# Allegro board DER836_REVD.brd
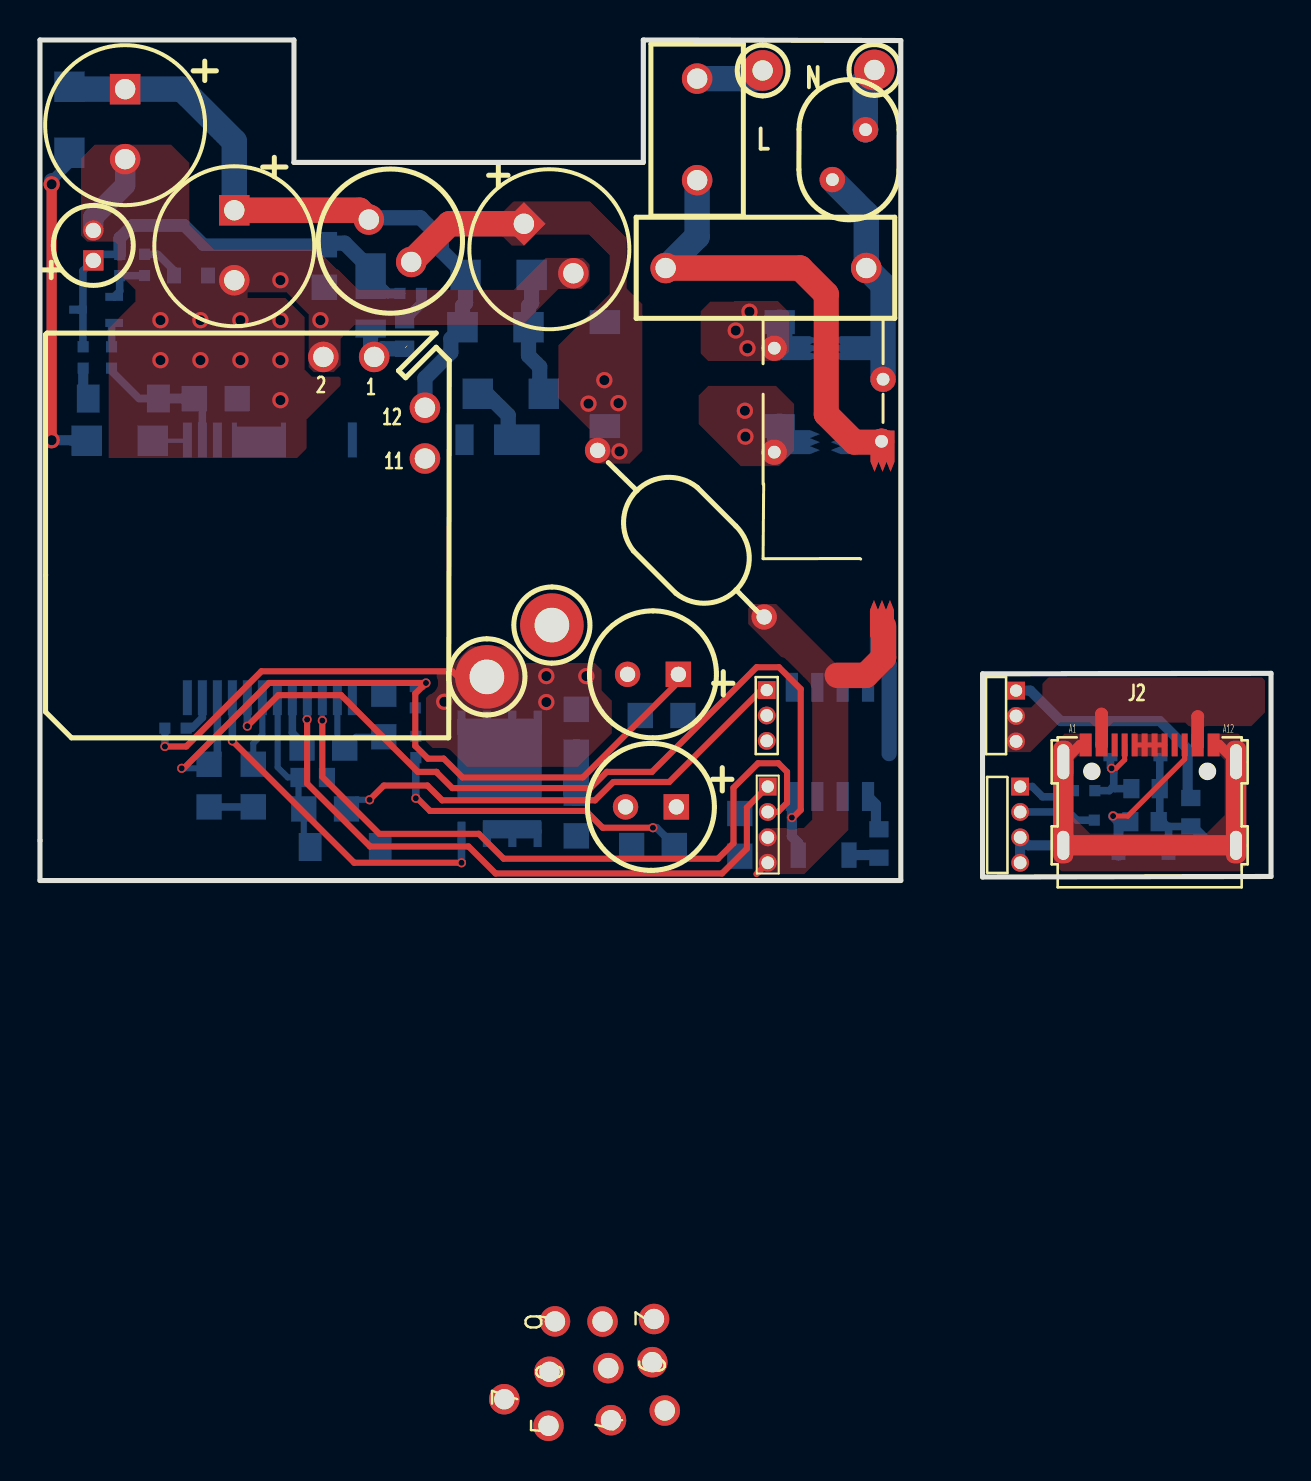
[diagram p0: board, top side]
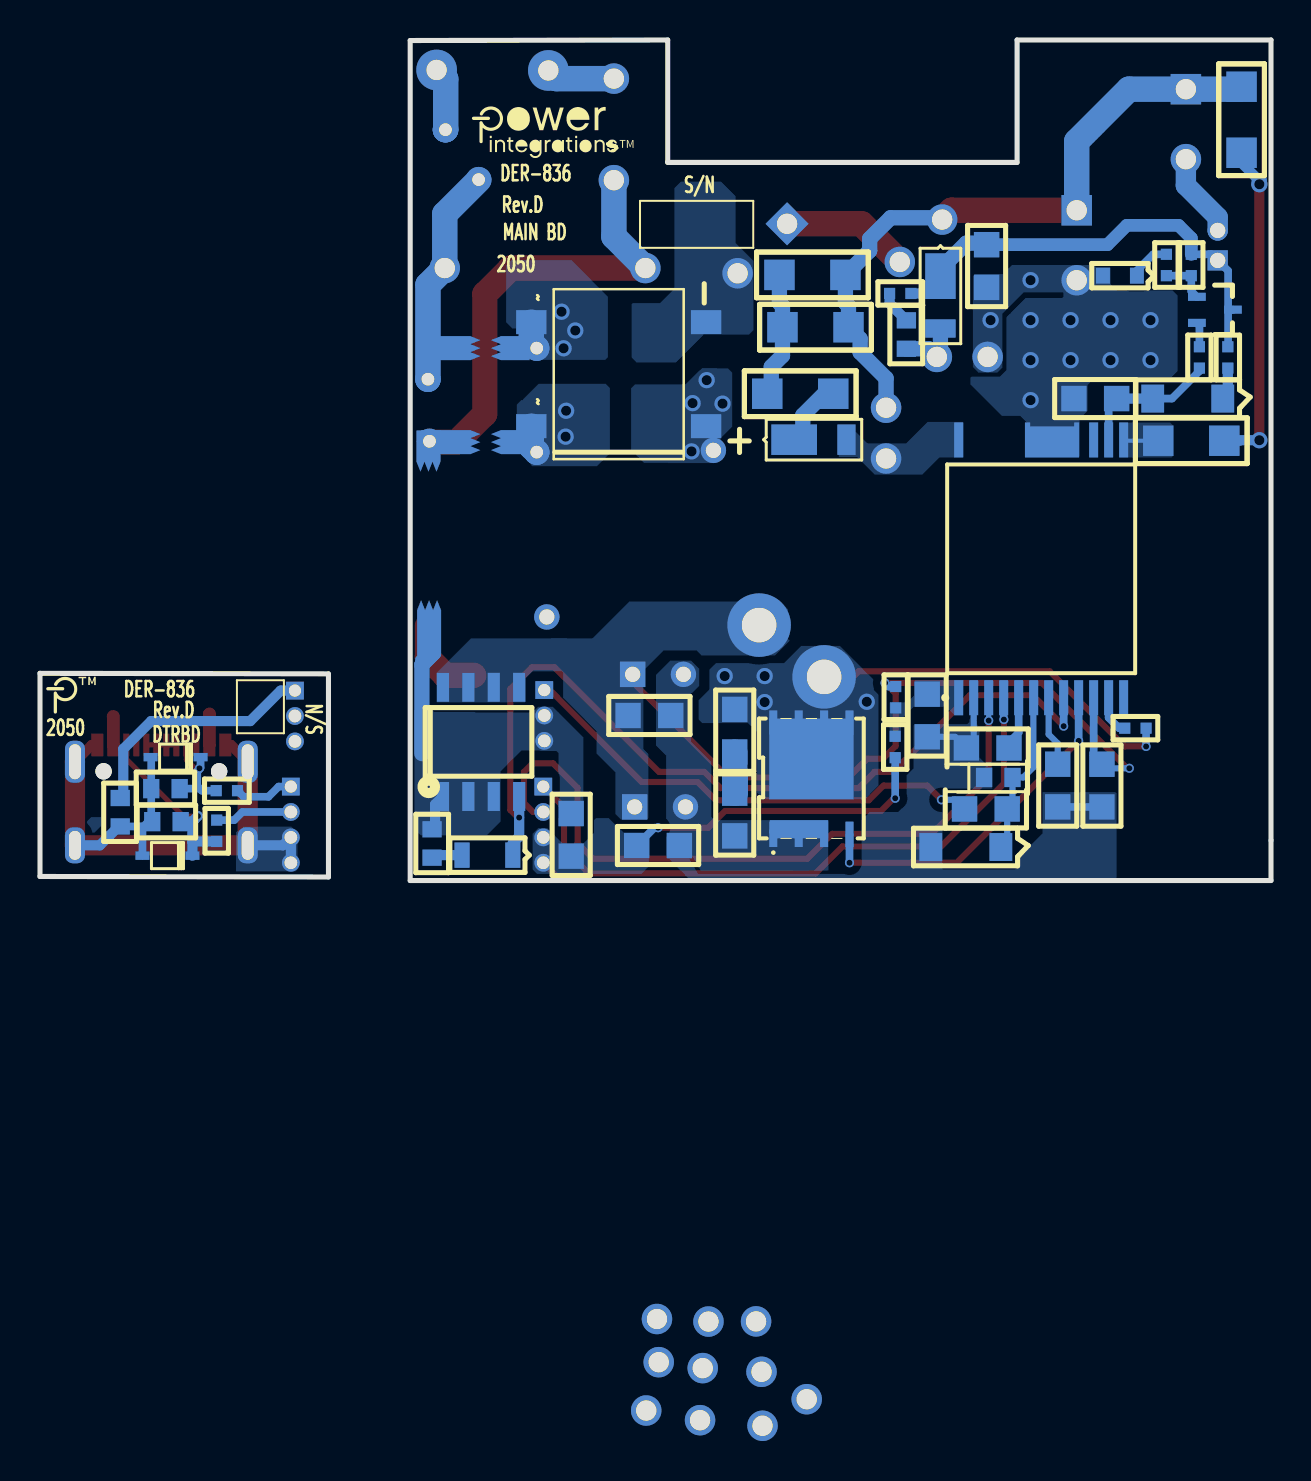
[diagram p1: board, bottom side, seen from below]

Outline 61.57 x 42.04 mm; copper layers: TOP, GND, VCC, BOTTOM. Coordinates in mm from the lower left corner of the outline.
Outline path: 0,42.04 12.7,42.04 12.7,35.91 30.17,35.91 30.17,42.04 43.03,42.01 43.05,42.01 43.05,0 0,0 0,42.04 ; 47.14,10.34 47.14,0.18 61.57,0.2 61.57,10.36 47.14,10.34

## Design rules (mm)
constraint set DEFAULT: min track width 0.203

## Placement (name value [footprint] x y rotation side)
BR1  MSB30M-13  [PISMD_4SMD_DF-S]  32.62 25.32 90 bottom
C1  100 nF  [PI_NP_XCAP_RAD512X197X395D040]  41.32 30.63 180 top
C2  18 uF  [PIPOLCAPCYLD3P5LS17LD40]  25.48 31.57 315 top
C3  18 uF  [PIPOLCAPCYLD3P5LS17LD40]  9.72 31.72 270 top
C4  2.2 nF  [PISMC1206]  24.43 27.67 180 bottom
C5  56 pF  [PISMC0603]  18.24 28.02 270 bottom
C6  22 uf  [PIPOLCAP4P0X11P0XLS1P5D030]  2.67 31.01 90 top
C7  470 nF  [PISMC0805]  7.72 24.1 0 bottom
C8  1 nF  [PISMC0805]  26.82 4.37 270 bottom
C9  470 pF  [PINPCAPRAD7MMXLS10MM030]  27.93 21.39 315 top
C10  470 uF  [PIPOLCAPCYLD250LS100030]  31.93 10.31 180 top
C11  470 uF  [PIPOLCAPCYLD250LS100030]  31.83 3.68 180 top
C12  1 uF  [PISMC0805]  32.16 8.25 180 bottom
C13  2.2 uF  [PISMC0805]  15.24 6.63 180 bottom
C14  4.7 uF  [PISMC0805]  17.19 7.19 90 bottom
C16  1 uF  [PISMC0805]  35 3.35 270 bottom
C17  560 pF  [PISMC0603]  54.58 4.6 0 bottom
C18  560 pF  [PISMC0603]  54.53 2.95 0 bottom
C19  18 uF  [PIPOLCAPCYLD3P5LS17LD40]  4.26 37.78 270 top
C20  2.2 uF  [PISMC0805]  10.67 3.68 90 bottom
C21  560 pF  [PISMC0603]  14.35 5.16 180 bottom
C22  2.2 uF  [PISMC0805]  8.46 3.68 90 bottom
C23  560 pF  [PISMC0805]  14.22 29.67 90 bottom
D1  DFLR1600-7  [PISMDDFLR120012]  23.88 22.05 0 bottom
D2  DFLR1200-7  [PISMDDFLR120012]  16.53 30.25 90 bottom
D3  BAV21WS-7-F  [PISMSOD323]  37.92 1.27 0 bottom
D4  MM3Z24VC  [PISMSOD323F]  53.54 6.17 0 bottom
D5  MM3Z24VC  [PISMSOD323F]  53.94 1.24 0 bottom
D6  MMSZ3V9T1G  [PI_SM_SOD-123_12]  13.51 1.68 0 bottom
F1  2 A  [PI_RST_MICROFUSE]  32.87 35.03 90 top
FL2  Hole_70mils  [PI_HOLE_70MIL]  25.6 12.75 0 top
FL3  Hole_70mils  [PI_HOLE_70MIL]  22.35 10.16 0 top
J2  CON16_USB_C  [USB_C_LM_U3231-096]  55.5 5.46 0 top
J3  CON3  [PI_HDR_1P27MM_3RA]  48.82 9.5 270 bottom
J4  CON3  [PI_HDR_1P27MM_3RA_DNL]  36.35 9.53 270 top
J5  CON4  [PI_HDR_1P27MM_4RA]  49.02 4.7 270 bottom
J6  CON4  [PI_HDR_1P27MM_4RA_DNL]  36.4 4.7 270 top
L1  8 mH  [PI_TOROID_CMC12X6_4P_V]  39.17 22.07 270 top
L2  220 uH  [PI_CHOKE_2P_LS118D283]  16.45 33.06 315 top
L3  Bead (Z=1K)  [PISMR0805]  15.33 3.58 180 bottom
NOREF  -  []  47.14 10.34 0 top
NOREF#2  -  []  0 42.04 0 top
NOREF#3  -  []  61.57 0.2 90 top
NOREF#4  -  []  0.02 0.02 90 top
NOREF#5  -  []  90.3 -219.28 0 top
NOREF#6  -  []  -328.68 -232.26 0 top
NOREF#7  -  []  40.52 38.6 180 bottom
NOREF#8  -  []  61.15 10.41 180 bottom
Q1  AO4354  [PISMSO8]  41.41 4.2 180 bottom
Q2  AON6220  [PISMPQFN5X6B]  24.89 2.31 180 bottom
Q5  MMST3904  [PISMSOT323132]  3.71 29.21 270 bottom
R1  1 M  [PISMR1206]  24.59 30.29 180 bottom
R2  10  [PISMR1206]  21.89 24.35 0 bottom
R3  100  [PISMR0402]  18.01 29.36 0 bottom
R5  22  [PISMR0402]  2.16 26.69 270 bottom
R6  2.00 M  [PISMR1206]  1.47 39.7 270 bottom
R7  1.80 M  [PISMR1206]  2.34 22 0 bottom
R8  10  [PISMR0805]  26.82 6.43 90 bottom
R9  100  [PISMR0603]  41.96 1.14 90 bottom
R10  47  [PISMR0402]  6.25 7.62 0 bottom
R11  0.009  [PISMR0805]  29.59 1.75 0 bottom
R12  160.0 k  [PISMR0402]  18.77 9.7 270 bottom
R13  10  [PISMR0402]  18.8 7.21 270 bottom
R14  22  [PISMR0402]  52.76 4.5 180 bottom
R15  22  [PISMR0402]  52.73 1.95 90 bottom
R16  6.34 k  [PISMR0402]  3.58 25.63 90 bottom
R17  47.0 k  [PISMR0402]  3.99 31.32 270 bottom
R18  4.22 k  [PISMR0402]  5.23 30.25 90 bottom
RT1  5  [PI_RAD_276DX197T_LS100D025]  40.46 37.55 269.9 top
RT2  100 k  [PISMR0603]  57.56 4.13 270 bottom
T1  RM8  [PI_BOBBIN_RM8_12P_CLP]  16.71 26.19 90 top
TP1  BLK  [PITPKEYSTONE100X100]  41.73 40.54 0 top
TP2  WHT  [PITPKEYSTONE100X100]  36.14 40.51 0 top
U1  InnoPPD  [PI_IC_INSOP_24D]  15.62 9.14 90 bottom
VR1  MMSZ5258B-7-F  [PI_SM_SOD-123_12]  2.41 24.1 0 bottom
VR2  DZ2S11000L  [PI_SM_D_SSMINI2P]  6.71 30.25 0 bottom

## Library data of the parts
BR1 = DIODE BRIDGE_+~-~
C1 = CAP NP: alternate symbols: (pi_np_xcap_rad512x197x395d040_h); room: 1
C2 C3 C19 = CAP POL: alternate symbols: (pipolcapcyld3p5ls17ld40H); room: 1
C4 C5 C7 = CAP NP: room: 1
C6 = CAP POL: alternate symbols: (pipolcap4p0x12p5xls1p5d030h); room: 1
C8 = CAP NP: alternate symbols: (pismc0805_1)
C9 C12-C14 C16-C18 C20-C23 = CAP NP
C10 C11 = CAP POL: alternate symbols: (pipolcapcyld250ls100030_h)
D1 D2 = DIODE: room: 1
D3 = DIODE
D4-D6 = DIODE_ZENER
F1 = FUSE: alternate symbols: (pirstmicrofusehoz); room: 1
FL2 FL3 = FlyingLead
J2 = USB_C_LM_U3231-096
J3 = CON3: alternate symbols: (pi_hdr_1p27mm_3RA_MB,pi_hdr_1p27mm_3RA_DNL)
J4 = CON3DNL: alternate symbols: (pi_hdr_1p27mm_3RA_MB,pi_hdr_1p27mm_3RA_DNL)
J5 = CON4: alternate symbols: (pi_hdr_1p27mm_4RA_MB,pi_hdr_1p27mm_4RA_DNL)
J6 = CON4DNL: alternate symbols: (pi_hdr_1p27mm_4RA_MB,pi_hdr_1p27mm_4RA_DNL)
L1 = TORRID 4P_21_34: alternate symbols: (pi_toroid_CMC12x6_4p_H)
L2 = INDUCTOR: alternate symbols: (pi_choke_2p_ls118d283H); room: 1
L3 = INDUCTOR_BEAD
Q1 = FET_N_SGD_123_4_5678
Q2 = FET_N_SGD_123_4_5678: room: 2
Q5 = NPN_BEC: room: 1
R1-R3 R5-R7 R16-R18 = R: room: 1
R8-R15 = R
RT1 = THERMISTOR: alternate symbols: (pi_rad_276DX197Tls100d025H); room: 1
RT2 = THERMISTOR
T1 = BRM8_12P_CLP: alternate symbols: (pi_bobbin_rm8_12p_clp); room: 1
TP1 TP2 = TESTPOINT: room: 1
U1 = DEV_InnoPPD: room: 1
VR1 VR2 = DIODE_ZENER: room: 1

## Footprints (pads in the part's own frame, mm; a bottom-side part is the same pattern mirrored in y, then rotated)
PI_BOBBIN_RM8_12P_CLP
  round 1.524 hole 1.016: 1(0,0) 2(0,2.54) 3(-48.115,-13.998) 4(-53.176,-11.843) 5(-53.455,-8.719) 6(-48.235,-9.042) 7(-52.127,-6.508) 8(-50.755,-8.769) 9(-50.274,-13.911) 10(-48.242,-11.422) 11(-5.08,-2.54) 12(-2.54,-2.54) CLP1(-50.571,-11.709) CLP2(-52.693,-14.536)
PI_CHOKE_2P_LS118D283
  round 1.524 hole 1.016: 1(0,0) 2(2.997,0)
PI_HDR_1P27MM_3RA
  rect 0.889x0.889 hole 0.61: 1(0,0)
  round 0.889 hole 0.635: 2(1.27,0) 3(2.54,0)
PI_HDR_1P27MM_3RA_DNL
  rect 0.889x0.889 hole 0.61: 1(0,0)
  round 0.889 hole 0.635: 2(1.27,0) 3(2.54,0)
PI_HDR_1P27MM_4RA
  rect 0.889x0.889 hole 0.61: 1(0,0)
  round 0.889 hole 0.635: 2(1.27,0) 3(2.54,0) 4(3.81,0)
PI_HDR_1P27MM_4RA_DNL
  rect 0.889x0.889 hole 0.61: 1(0,0)
  round 0.889 hole 0.635: 2(1.27,0) 3(2.54,0) 4(3.81,0)
PI_HOLE_70MIL
  round 3.175 hole 1.727: 1(0,0.025)
PI_IC_INSOP_24D
  rect 1.75x0.45 smd: 1(0,0) 2(0,-0.75) 3(0,-1.5) 4(0,-2.25) 5(0,-3) 6(0,-3.75) 7(0,-4.5) 8(0,-5.25) 9(0,-6) 10(0,-6.75) 11(0,-7.5) 12(0,-8.25) 13(12.89,-8.25) 14(12.89,-7.5) 15(12.89,-6.75) 24(12.89,0)
  custom 0.438x0.438 smd: 16(12.89,-4.67)
PI_NP_XCAP_RAD512X197X395D040
  round 1.524 hole 1.016: 1(0,0) 2(10.033,0)
PI_RAD_276DX197T_LS100D025
  round 1.27 hole 0.635: 1(0,0.825) 2(2.5,-0.825)
PI_RST_MICROFUSE
  round 1.524 hole 1.016: 1(0,0) 2(5.08,0)
PI_SM_D_SSMINI2P
  rect 0.698x0.8 smd: 1(0,0) 2(1.7,0)
PI_SM_SOD-123_12
  rect 1.143x1.397 smd: 1(0,0) 2(3.505,0)
PI_TOROID_CMC12X6_4P_V
  round 1.27 hole 0.635: 1(-3,3) 2(-4.553,-2.441) 3(0.647,-2.441) 4(0.104,2.924)
PINPCAPRAD7MMXLS10MM030
  round 1.27 hole 0.762: 1(-0.119,0.054) 2(11.663,0.054)
PIPOLCAP4P0X11P0XLS1P5D030
  rect 1.016x1.016 hole 0.762: 1(0,0)
  round 1.016 hole 0.762: 2(1.5,0)
PIPOLCAPCYLD3P5LS17LD40
  rect 1.524x1.524 hole 1.016: 1(-1.8,0)
  round 1.524 hole 1.016: 2(1.7,0)
PIPOLCAPCYLD250LS100030
  rect 1.27x1.27 hole 0.762: 1(0,0)
  round 1.27 hole 0.762: 2(2.54,0)
PISMC0603
  rect 0.813x0.965 smd: 1(0,0) 2(1.422,0)
PISMC0805
  rect 1.27x1.27 smd: 1(0,0) 2(2.134,0)
PISMC1206
  rect 1.524x1.524 smd: 1(0,0) 2(3.302,0)
PISMD_4SMD_DF-S
  rect 1.2x1.52 smd: 1(-2.6,-4.37) 2(-2.6,4.37) 3(2.6,-4.37) 4(2.6,4.37)
PISMDDFLR120012
  rect 2.286x1.524 smd: 1(-0.025,0)
  rect 0.914x1.524 smd: 2(-2.642,0)
PISMPQFN5X6B
  rect 0.406x1.27 smd: 1(0,0) 2(1.27,0) 3(2.54,0) 4(3.81,0)
  rect 0.406x1.219 smd: 5(3.81,5.588) 6(2.54,5.588) 7(1.27,5.588) 8(0,5.588)
PISMR0402
  rect 0.559x0.559 smd: 1(0,0) 2(1.067,0)
PISMR0603
  rect 0.813x0.965 smd: 1(0,0) 2(1.422,0)
PISMR0805
  rect 1.27x1.27 smd: 1(0,0) 2(2.134,0)
PISMR1206
  rect 1.524x1.524 smd: 1(0,0) 2(3.302,0)
PISMSO8
  rect 0.61x1.448 smd: 1(0,0) 2(1.27,0) 3(2.54,0) 4(3.81,0) 5(3.81,5.461) 6(2.54,5.461) 7(1.27,5.461) 8(0,5.461)
PISMSOD323
  rect 0.762x1.27 smd: 1(0,0) 2(2.54,0)
PISMSOD323F
  rect 0.7x0.42 smd: 1(0,0) 2(2.5,0)
PISMSOT323132
  rect 0.406x0.889 smd: 1(0.018,0) 2(1.321,0) 3(0.66,1.803)
PITPKEYSTONE100X100
  round 2.032 hole 1.016: 1(0,0)
USB_C_LM_U3231-096
  round 0.813 hole 0.813: (-2.89,0) (2.89,0)
  rect 0.6x1.14 smd: A1B12(-3.2,1.32) A4B9(-2.4,1.32) A9B4(2.4,1.32) A12B1(3.2,1.32)
  rect 0.3x1.14 smd: A5(-1.25,1.32) A6(-0.25,1.32) A7(0.25,1.32) A8(1.25,1.32) B5(1.75,1.32) B6(0.75,1.32) B7(-0.75,1.32) B8(-1.75,1.32)
  rrect 1x2.1 hole 0.6x1.75: S1(-4.32,0.48) S4(4.32,0.48)
  rrect 1x1.8 hole 0.6x1.45: S2(-4.32,-3.7) S3(4.32,-3.7)

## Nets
GND: C8.2 C10.2 C11.2 C12.2 C13.1 C14.1 C20.1 C21.1 C22.1 D6.2 Q2.1 Q2.2 Q2.3(S3) R11.1 U1.2
VBUS: C16.1 J2.A4B9 J2.A9B4 J3.2 J3.3 J4.2 J4.3 Q1.1 Q1.2 Q1.3(S3) R9.2
CC1: J5.1 J6.1 R14.2 U1.4
CC2: J5.2 J6.2 R15.2 U1.3
NTC: J3.1 J4.1 L3.1 RT2.1
RTN: C9.2 C16.2 C17.2 C18.2 D4.2 D5.2 J2.A1B12 J2.A12B1 J2.S1 J2.S2 J2.S3 J2.S4 J5.3 J5.4 J6.3 J6.4 R11.2 R13.2 RT2.2
N2052921: C10.1 C11.1 C12.1 C22.2 FL2.1 Q1.5 Q1.6 Q1.7 Q1.8 R12.1 U1.10(VOUT)
N2239928: D1.2 T1.11 U1.24
N2245604: FL3.1 Q2.5 Q2.6 Q2.7 Q2.8 R8.2 R10.1
N2254675: C4.1 R1.1 R2.2
N2666518: R10.2 U1.11
N2728118: C3.1 C4.2 C19.1 L2.1 R1.2 R6.1 T1.12
N2729572: Q2.4 U1.9
N2741729: D1.1 R2.1
N2930599: BR1.1 C2.1 C9.1 L2.2
N2930737: BR1.2 L1.3
N2993096: C6.1 C23.2 D2.1 Q5.3 R3.1 R5.1 R17.1
N2993205: R5.2 VR1.1
N11157505: C13.2 U1.5
N11377564: F1.2 TP2.1
N11380424: C5.2 D2.2 T1.1
N11391845: C7.1 R16.1 U1.14 VR1.2
N11927756: D3.2 R9.1
N12044766: C17.1 D4.1 J2.A5 R14.1
N12044947: C18.1 D5.1 J2.B5 R15.1
N12067975: D3.1 Q1.4 U1.8
N12141120: C14.2 R12.2 R13.1 U1.1
N12170699: R6.2 R7.1
N12179865: BR1.4 L1.2
N12190252: RT1.1 TP1.1
N12194815: C1.2 F1.1 L1.4
N12195805: C1.1 L1.1 RT1.2
N12223753: C21.2 D6.1 L3.2 U1.6
N12224616: C20.2 U1.7
N12340123: J2.A6 J2.A7 J2.B6 J2.B7
N12362261: Q5.1 R17.2 R18.1
N12362291: Q5.2(EMITTER) R16.2
N12362317: R18.2 VR2.1
N12386710: BR1.3 C2.2 C3.2 C6.2 C7.2 C19.2 C23.1 T1.2 U1.16 VR2.2
N12387437: R7.2 U1.13
N27226770: C8.1 R8.1
N123505821: C5.1 R3.2

Pads without a net: J2 A8 B8; T1 3 4 5 6 7 8 9 10 CLP1 CLP2; U1 12 15

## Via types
v1: diameter 0.813, hole 0.508, TOP to BOTTOM, 26 vias
v2: diameter 0.457, hole 0.305, TOP to BOTTOM, 14 vias

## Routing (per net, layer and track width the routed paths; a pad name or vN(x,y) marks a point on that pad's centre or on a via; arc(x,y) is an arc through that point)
GND: length 7.5
  BOTTOM w0.203: C14.1 17.12,7.11 ; Q2.1 24.99,2.41 24.99,2.49 ; Q2.3 22.4,2.26
  BOTTOM w0.305: U1.2 14.87,7 C13.1 15.8,7.19 C14.1
  BOTTOM w0.381: C22.1 C20.1
VBUS: length 35.9
  TOP w0.254: J3.3 48.84,6.93
  TOP w0.635: 53.09,8.33 53.1,8.32 J2.A4B9 ; J2.A9B4 57.9,8.19 57.91,8.2
  GND w0.508: 48.79,6.99 J3.3 ; 48.79,8.25 J3.2
  VCC w0.254: J3.3 48.79,6.99 J4.3 ; J3.2 48.79,8.25 J4.2
  BOTTOM w0.508: R9.2 41.81,2.72 41.81,3.81 Q1.1
  BOTTOM w0.762: 42.47,6.35 42.47,10.79 41.91,11.35 41.91,12.06 41.93,12.09
CC1: length 47.8
  TOP w0.305: J6.1 35.36,3.66 35.36,1.6 34.11,0.36 22.78,0.36 21.44,1.7 16.51,1.7 13.36,4.85 v2(13.36,8.05)
  VCC w0.254: J6.1 J5.1
  BOTTOM w0.381: U1.4 13.37,8.06 v2(13.36,8.05) ; J5.1 49.63,4.7 50.14,4.19 51.38,4.19 R14.2
CC2: length 51.9
  TOP w0.254: J5.2 49.05,3.4
  TOP w0.305: J6.2 36.91,3.43 37.36,3.89 37.36,5.44 36.93,5.87 35.92,5.87 34.68,4.63 34.68,1.87 33.91,1.09 23.19,1.09 21.95,2.34 16.97,2.34 14.12,5.18 v2(14.12,8)
  VCC w0.254: J6.2 J5.2
  BOTTOM w0.254: U1.3 v2(14.12,8)
  BOTTOM w0.381: R15.2 51.85,3.02 51.45,3.43 J5.2
NTC: length 48.9
  TOP w0.305: J4.1 36.07,9.53 31.47,4.93 28.68,4.93 27.76,4.01 20.12,4.01 19.38,4.75 17.2,4.75 v2(16.48,4.04)
  GND w0.508: 48.79,9.53 J3.1
  VCC w0.254: J3.1 48.79,9.53 J4.1
  BOTTOM w0.305: v2(16.48,4.04) 15.79,4.04 L3.1
  BOTTOM w0.508: J3.1 49.53,9.5 51.05,7.98 56.01,7.98 57.4,6.58 57.4,4.28 RT2.1
RTN: length 79
  TOP w0.305: 35.83,0.32 35.94,0.43 J6.4 ; v2(18.8,4.11) 18.87,4.11 19.51,3.48 27.3,3.48 28.14,2.64 v2(30.66,2.64)
  TOP w0.508: J2.A12B1 58.98,6.78 J2.S4 ; J2.A1B12 52.02,6.78 J2.S1
  TOP w0.762: 39.8,10.34 39.88,10.26
  TOP w1.016: J2.S4 J2.S3 J2.S2 J2.S1
  TOP w1.27: 42.19,12.72 42.19,11.15 41.3,10.26 39.88,10.26
  VCC w0.254: J6.4 J5.4 ; J6.3 J5.3
  BOTTOM w0.381: RT2.2 56.49,2.71 56.44,2.66 ; v2(30.66,2.64) 30.84,2.64 R11.2 ; D4.2 56.01,6.14 C17.2 56.01,3 C18.2 56.15,2.95 56.44,2.66 ; 56.44,2.66 D5.2 ; R13.2 v2(18.8,4.11)
  BOTTOM w0.508: J2.S3 58.58,1.76 57.63,2.71 RT2.2 ; J5.4 J5.3 49.42,1.76 J2.S2 51.25,1.83
N2052921: length 39.1
  TOP w0.305: v2(7.09,5.61) 7.19,5.61 11.45,9.88 v2(19.3,9.88) 18.77,9.35 18.77,6.73 19.41,6.1 20.19,6.1 21.13,5.16 27.15,5.16 31.93,9.93 C10.1
  BOTTOM w0.305: v2(7.09,5.61) 8.25,5.61 C22.2
  BOTTOM w0.381: U1.10 8.87,6.23 C22.2 ; R12.1 19.13,9.7 v2(19.3,9.88)
N2245604: length 19
  TOP w0.305: v2(6.25,6.71) 7.31,6.71 11.07,10.46 20.62,10.46 21.34,9.75 21.92,9.75
  TOP w0.381: FL3.1 21.92,9.75
  BOTTOM w0.381: R10.1 v2(6.25,6.71)
  vias: v1(20.22,8.94) v1(25.32,10.22) v1(25.32,8.92) v1(27.32,10.22)
N2254675: length 6.3
  BOTTOM w0.762: R2.2 24.99,24.55 24.99,25.69 24.43,26.25 C4.1 24.43,28.74 24.59,28.89 R1.1
N2666518: length 2
  BOTTOM w0.381: R10.2 7.59,7.62 8.12,8.15 U1.11
N2728118: length 33.7
  TOP w0.203: 19.3,23.7 T1.12
  TOP w1.27: L2.1 15.98,33.52 9.72,33.52 C3.1
  BOTTOM w0.762: L2.1 16.54,33.15 19.02,33.15 20.07,32.1 20.07,31.5 R1.2 21.28,28.89 21.13,28.74 C4.2 20.55,27.09 20.55,26.42 19.25,25.12 T1.12
  BOTTOM w1.27: C3.1 9.72,36.97 7.11,39.58 C19.1 1.59,39.58 R6.1
N2729572: length 17.6
  TOP w0.305: v2(21.08,0.89) 15.72,0.89 v2(9.62,6.98)
  BOTTOM w0.381: Q2.4 v2(21.08,0.89) ; U1.9 v2(9.62,6.98)
N2741729: length 3.4
  BOTTOM w0.762: D1.1 23.42,22.48 23.42,23.27 22.34,24.35 R2.1
N2930599: length 6.4
  TOP w1.27: C2.1 20.48,32.84 L2.2
  vias: v1(27.43,23.85) v1(28.22,25.02) v1(28.93,23.88) v1(28.98,21.46)
N2930737: length 1.4
  BOTTOM w1.27: BR1.2 36.99,21.69 L1.3
  vias: v1(35.25,23.49) v1(35.28,22.2)
N2993096: length 23
  BOTTOM w0.381: Q5.3 1.9,28.55 2.15,28.55 ; R5.1 2.15,26.71 2.15,28.55 ; R17.1 2.97,31.32 C6.1 2.15,30.49 2.15,28.55
  BOTTOM w0.508: D2.1 17.4,29.36 R3.1
  BOTTOM w0.635: C23.2 8.18,31.8 7.21,32.77 4.62,32.77 3.99,32.13 R17.1
  BOTTOM w0.762: C23.2 14.3,31.88 15.24,31.88 16.53,30.58 D2.1
N2993205: length 1.6
  BOTTOM w0.508: R5.2 2.16,24.36 VR1.1
N11157505: length 2.7
  BOTTOM w0.381: C13.2 13.11,6.91 12.62,7.39 U1.5
N11377564: length 3.4
  BOTTOM w1.27: TP2.1 35.74,40.11 F1.2
N11380424: length 3.2
  BOTTOM w0.762: C5.2 17.12,26.59 T1.1 16.53,26.37 D2.2
N11391845: length 7.1
  BOTTOM w0.381: C7.1 8.12,23.7 U1.14 ; VR1.2 4.95,24.1 3.58,25.48 R16.1
  BOTTOM w0.508: VR1.2 C7.1
N11927756: length 1.6
  BOTTOM w0.508: D3.2 41.83,1.27 R9.1
N12044766: length 5.4
  TOP w0.254: v2(53.59,5.61) 53.82,5.61 54.25,6.04 J2.A5
  BOTTOM w0.254: v2(53.59,5.61) 53.59,5.49 53.7,5.38
  BOTTOM w0.381: 53.7,4.65 53.64,4.65 53.48,4.5 R14.1 ; 53.7,4.65 53.7,5.48 53.54,5.64 D4.1 ; 53.7,4.65 53.76,4.6 C17.1
N12044947: length 9.4
  TOP w0.254: J2.B5 57.25,6.07 54.41,3.23 v2(53.67,3.23)
  BOTTOM w0.508: D5.1 53.94,1.93 ; 53.94,1.93 53.94,2.94 53.95,2.95 ; 53.94,1.93 53.92,1.95 R15.1 ; C18.1 53.95,2.95 ; 53.95,2.95 v2(53.67,3.23)
N12067975: length 44.4
  TOP w0.305: v2(37.6,3.15) 37.67,3.15 38.05,3.53 38.05,9.58 36.96,10.67 35.84,10.67 30.61,5.44 28.35,5.44 27.53,4.62 20.62,4.62 19.84,5.41 19.84,5.44 18.9,5.44 15.06,9.27 11.92,9.27 v2(10.37,7.72)
  BOTTOM w0.381: v2(10.37,7.72) 10.37,9.14 U1.8
  BOTTOM w0.508: D3.1 37.92,1.88 37.6,2.2 v2(37.6,3.15) Q1.4
N12170699: length 17.3
  TOP w0.508: v1(0.58,34.82) v1(0.58,22.02)
  BOTTOM w0.508: 0.58,35 1.47,35.89 R6.2 ; 1.57,22 R7.1 2.31,22.02 v1(0.58,22.02)
  BOTTOM w0.762: v1(0.58,34.82) 0.58,35
N12179865: length 1.4
  BOTTOM w1.27: L1.2 36.99,26.89 BR1.4
  vias: v1(34.8,27.51) v1(35.38,26.62) v1(35.48,28.45)
N12190252: length 3.2
  BOTTOM w1.27: RT1.1 41.28,37.56 41.28,40.08 TP1.1
N12194815: length 23
  TOP w1.25: L1.4 42.09,21.97 42.05,21.92 40.72,21.92 39.32,23.32 39.32,29.33
  TOP w1.27: 39.32,29.33 38.02,30.63 C1.2
  BOTTOM w1.27: C1.2 32.87,32.21 F1.1
N12195805: length 11
  BOTTOM w0.203: 39.62,35.04 39.63,35.05 RT1.2
  BOTTOM w1.27: 39.62,35.04 41.32,33.33 C1.1 42.17,29.79 L1.1
N12223753: length 8.5
  BOTTOM w0.305: D6.1 13.19,1.99 L3.2 12.93,3.85 C21.2 12.39,5.16 11.89,5.66 11.89,9.13 U1.6
N12224616: length 3.5
  BOTTOM w0.305: U1.7 11.12,7.31 10.67,6.86 C20.2
N12340123: length 1.5
  TOP w0.254: J2.B7 J2.A6 J2.A7 J2.B6
N12362261: length 2.4
  BOTTOM w0.381: R18.1 R17.2 3.99,29.47 Q5.1
N12362291: length 1.2
  BOTTOM w0.381: R16.2 3.58,27.76 Q5.2
N12362317: length 2.1
  BOTTOM w0.381: R18.2 5.89,31.32 6.71,30.5 VR2.1
N12386710: length 5.3
  BOTTOM w0.203: U1.16 10.86,22.13 10.86,22.56 ; 9.36,30.33 9.41,30.33 C3.2
  BOTTOM w1.016: C19.2 4.26,34.76 2.67,33.17 C6.2
  vias: v1(6.02,28.02) v1(6.02,26.02) v1(8.02,28.02) v1(8.02,26.02) v1(10.02,28.02) v1(10.02,26.02) v1(12.02,30.02) v1(12.02,28.02) v1(12.02,26.02) v1(12.02,24.02) v1(14.02,28.02)
N12387437: length 1.7
  BOTTOM w0.203: R7.2 7.33,22 U1.13
N27226770: length 2.1
  BOTTOM w1.27: R8.1 26.82,5.1 26.8,5.08 26.8,4.39 C8.1
N123505821: length 1.7
  BOTTOM w0.508: R3.2 19.08,28.86 C5.1

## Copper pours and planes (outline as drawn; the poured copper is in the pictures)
GND on BOTTOM (solid shape): 25.07,2.11 22.15,2.11 22.15,3.02 25.07,3.02
GND on BOTTOM: 22.15,3.02 27.84,3.02 27.99,3.17 27.99,5.92 29.01,6.93 29.01,9.35 28.98,9.35 28.6,9.73 28.6,10.59 29.01,11 30.05,11 30.76,10.29 30.76,6.76 30.25,6.25 30.25,1.22 29.16,0.13 7.75,0.13 7.72,0.15 7.72,4.37 7.77,4.42 11.43,4.42 11.43,2.36 12.62,1.17 12.62,0.74 12.8,0.56 16.52,0.56 16.56,0.6 20.79,0.6 21.06,0.33 28.66,0.33 29.13,1.17 29.13,1.19 29.03,1.27 28.98,1.27 28.5,0.47 22.13,0.5 22.17,3
GND on BOTTOM: 15.19,7.82 17.8,7.82 17.88,7.75 17.88,5.61 18.24,5.26 18.24,3.83 18.64,3.43 20.07,3.43 20.47,3.02 20.47,0.89 20.78,0.58 20.78,0.38 16.51,0.38 16.43,0.46 16.43,3.45 16.94,3.96 16.94,4.22 16.56,4.6 13.94,4.6 13.94,5.69 14.12,5.69 14.58,6.15 14.58,7.67 14.63,7.72 14.63,10.01 14.6,10.03 15.06,10.03 15.09,10.01 15.09,7.92
VBUS on BOTTOM (solid shape): 42.71,13.52 42.71,11.23 42.8,11.14 42.8,10.46 42.57,10.24 42.5,10.24 41.51,11.23 41.51,13.52 41.71,14.02 41.91,13.52 42.11,14.02 42.31,13.52 42.51,14.02
VBUS on TOP: 48.28,6.53 48.28,8.33 48.61,8.66 49.58,8.66 50.14,9.22 50.14,9.85 50.44,10.16 61.11,10.16 61.26,10.01 61.26,8.41 60.58,7.72 58.42,7.72 58.22,7.52 58.22,6.22 57.61,6.22 57.58,6.25 57.58,7.59 57.28,7.9 53.64,7.9 53.39,7.64 53.39,6.22 52.78,6.22 52.78,7.64 52.53,7.9 51,7.9 49.53,6.43 48.39,6.43
VBUS on BOTTOM: 36.09,8.69 36.65,8.69 36.93,8.41 39.8,8.41 39.83,8.43 41.86,8.43 42.21,8.79 42.57,8.79 42.85,8.51 42.85,2.59 42.52,2.26 39.22,2.26 38.99,2.49 38.53,2.95 38.53,5.46 37.49,6.5 36.14,6.5 35.79,6.86 35.79,8.38
VBUS on BOTTOM: 34.39,2.72 34.39,7.16 35.91,8.69 36.65,8.69 36.93,8.41 36.93,6.88 36.52,6.48 35.74,6.48 35.64,6.37 35.64,2.72
Net_1 on BOTTOM: 55.68,6.37 55.68,5.64 55.4,5.36 55.4,2.06 56.08,1.37 56.74,1.37 56.95,1.57 59.21,1.57 59.28,1.5 59.44,1.65 59.44,2.74 59,3.17 57.05,3.17 56.44,3.78 56.44,6.37
Net_9 on BOTTOM (solid shape): 39.01,22.32 38.51,22.12 39.01,21.92 38.51,21.72 39.01,21.53 38.51,21.32 36.8,21.32 36.8,22.52 38.51,22.52
Net_9 on BOTTOM (solid shape): 42.51,26.02 40.04,26.02 39.54,26.22 40.04,26.42 39.54,26.62 40.04,26.82 39.54,27.02 40.04,27.22 42.51,27.22
Net_9 on BOTTOM (solid shape): 42.51,21.32 40.04,21.32 39.54,21.53 40.04,21.72 39.54,21.92 40.04,22.12 39.54,22.32 40.04,22.52 42.51,22.52
Net_9 on BOTTOM (solid shape): 39.01,27.02 38.51,26.82 39.01,26.62 38.51,26.42 39.01,26.22 38.51,26.02 37.08,26.02 37.08,27.2 37.11,27.22 38.51,27.22
RTN on TOP (solid shape): 42.71,13.53 42.71,12.08 41.63,12.08 41.63,12.09 41.51,12.21 41.51,13.53 41.71,14.03 41.91,13.53 42.11,14.03 42.31,13.53 42.51,14.03
RTN on TOP: 52.58,7.34 51.23,7.34 50.67,6.78 50.67,5.41 50.8,5.28 51.61,5.28 51.69,5.36 51.69,6.02 51.89,6.22 52.58,6.22 52.6,6.2 52.6,7.31
RTN on TOP: 35.82,2.22 35.82,0.52 36.02,0.32 38.22,0.32 40.42,2.52 40.42,10.22 36.82,13.83 35.65,13.83 35.42,13.61 35.42,12.82 38.62,9.62 38.62,3.04 38.21,2.62 36.22,2.62
RTN on TOP: 58.39,7.37 59.92,7.37 60.35,6.93 60.35,0.79 60.02,0.46 51.1,0.46 50.7,0.86 50.7,5.41 50.8,5.51 51.59,4.72 51.59,3.28 52.53,2.34 58.32,2.34 59.26,3.28 59.26,6.02 59.05,6.22 58.42,6.22 58.39,6.25
RTN on BOTTOM: 48.69,2.44 48.69,0.66 48.64,0.61 48.79,0.46 51.76,0.46 51.76,2.41 51.49,2.69 49,2.69 48.74,2.44
RTN on BOTTOM: 36.2,2.62 36.65,2.62 36.93,2.34 36.93,0.56 36.7,0.33 31.5,0.33 31.12,0.71 31.12,2.36 32.33,2.36 33.1,3.12 33.76,3.12 33.86,3.02 33.86,2.39 34.37,1.88 35.46,1.88
N2052921 on BOTTOM: 41.73,8.91 41.73,10.39 40.01,12.11 35.25,12.11 35.25,10.54 35.33,10.46 36.93,10.46 37.27,10.12 37.27,8.95 37.31,8.91
N2052921 on BOTTOM: 33.93,12.11 35.94,12.11 36.04,12.01 36.04,11.05 35.41,10.41 35.41,9.14 33.73,7.47 33.73,6.35 32.79,5.41 32.79,3.33 32.51,3.05 31.14,3.05 31.14,6.32 31.39,6.58 31.39,10.49 30.38,11.51 28.73,11.51 28.47,11.25 24.81,11.25 24.07,12 24.16,12.08 24.16,13.56 24.55,13.96 32.09,13.96
N2239928 on BOTTOM: 15.42,22.94 17.17,22.94 18.24,21.87 20.19,21.87 20.75,22.43 21.61,22.43 21.61,21.18 20.7,21.18 19.81,20.29 17.45,20.29 16.59,21.16 15.39,21.16 15.39,22.91
N2245604 on BOTTOM (solid shape): 25.09,4.06 20.88,4.06 20.88,8.1 25.09,8.1
N2245604 on TOP: 21.54,11.71 23.47,11.71 24.31,10.87 27.76,10.87 28.09,10.54 28.09,9.5 28.6,8.99 28.6,7.36 26.85,5.61 21.39,5.61 20.5,6.5 19.76,6.5 19.3,6.96 19.3,9.17 19.84,9.7 19.84,10.36 19.96,10.49 20.32,10.49 20.32,10.49
N2245604 on BOTTOM: 21.56,11.73 23.5,11.73 24.36,10.87 27.76,10.87 28.09,10.54 28.09,9.55 28.17,9.47 28.62,9.02 28.62,8.05 28.45,7.87 26.16,7.87 25.7,7.42 25.7,4.39 25.37,4.06 20.29,4.06 20.07,4.29 20.07,4.32 19.63,4.75 19.63,9.3 19.86,9.52 19.86,10.03 20.32,10.49
N2930599 on TOP: 25.92,26.76 25.92,24.12 27.48,22.57 27.48,21.26 27.89,20.85 29.49,20.85 30.12,21.49 30.12,28.83 29.34,29.62 29.34,32.13 27.51,33.96 23.67,33.96 23.01,33.3 23.01,32.33 23.6,31.75 24.23,31.75 24.79,32.31 27.46,32.31 28.5,31.27 28.5,29.34
N2930599 on BOTTOM: 28.27,25.62 27.72,25.62 27.72,25.62 27.17,25.62 26.95,25.4 26.95,22.7 27.52,22.12 27.52,21.22 27.86,20.88 30.15,20.88 30.16,20.89 31.36,20.89 32,21.54 32,24.61 31.8,24.82 29.29,24.82 28.6,25.5 28.57,25.5 28.45,25.63 28.27,25.63
N2930737 on TOP: 37.72,23.82 37.72,21.49 36.96,20.73 35.05,20.73 32.94,22.83 32.94,24.26 33.43,24.74 36.8,24.74
N2930737 on BOTTOM: 37.72,21.49 37.72,23.8 37.49,24.03 37.41,24.03 37.41,24.05 36.63,24.84 33.27,24.84 33.07,24.64 33.07,21.36 33.71,20.73 36.96,20.73
N12141120 on BOTTOM: 15.39,10.01 17.8,10.01 17.86,9.96 17.86,9.24 18.19,8.91 19.05,8.91 19.07,8.89 19.07,6.96 19.05,6.93 18.52,6.93 18.52,8.05 17.88,8.69 16.26,8.69 15.82,8.25 15.42,8.25 15.39,8.28
N12179865 on TOP: 37.46,26.44 37.46,28.42 36.91,28.98 34.72,28.98 34.68,28.94 33.51,28.94 33.04,28.47 33.04,26.36 33.43,25.98 37.01,25.98
N12179865 on BOTTOM: 36.47,26.03 33.3,26.03 33.17,26.16 33.17,29.21 34.98,31.01 38,31.01 38.25,30.76 38.25,27.91 37.67,27.33 36.73,27.33 36.7,27.36 36.47,27.13
N12194815 on TOP (solid shape): 41.56,22.5 42.74,22.5 42.74,20.95 42.54,20.45 42.34,20.95 42.14,20.45 41.94,20.95 41.74,20.45 41.54,20.95 41.54,22.53
N12194815 on BOTTOM (solid shape): 41.56,22.5 42.74,22.5 42.74,20.95 42.54,20.45 42.34,20.95 42.14,20.45 41.94,20.95 41.74,20.45 41.54,20.95 41.54,22.53
N12340123 on TOP: 54.62,7.32 54.62,6.22 56.32,6.22 56.32,7.32
N12386710 on TOP: 6.55,36.8 7.47,35.89 7.47,32.79 8.71,31.55 13.87,31.55 14.83,30.58 14.88,30.58 15.92,29.54 23.7,29.54 25.3,31.14 27.15,31.14 27.48,30.81 27.48,30 27.08,29.59 25.93,29.59 24.13,27.79 15.72,27.79 15.04,27.1 15.04,25.78 14.68,25.42 13.69,25.42 13.44,25.68 13.44,28.32 12.34,29.41 10.39,29.41 10.39,29.13 12.27,29.13 13.23,28.17 13.23,25.55 13.59,25.2 14.96,25.2 15.04,25.12 15.04,24.77 13.33,23.06 13.33,21.61 12.85,21.13 3.44,21.13 3.44,27.62 4.77,28.96 4.77,29.54 3.96,30.35 3.89,30.35 3.89,31.8 3.73,31.95 2.36,31.95 2.06,32.26 2.06,36.12 2.74,36.8
N12386710 on BOTTOM: 9.57,21.21 9.57,23.09 9.17,23.5 9.17,24.79 8.79,25.17 4.98,25.17 4.67,25.48 4.67,29.26 4.93,29.51 7.72,29.51 8.03,29.82 8.03,30.66 8.74,30.65 8.86,30.78 12.95,30.78 13.41,30.33 14.81,30.33 14.91,30.23 14.91,25.68 14.63,25.4 13.69,25.4 13.44,25.65 13.44,28.35 12.37,29.41 10.39,29.41 10.39,29.18 10.44,29.13 12.27,29.13 13.23,28.17 13.23,25.53 13.56,25.2 14.99,25.2 15.04,25.15 15.04,24.82 13.46,23.24 12.55,23.24 12.14,22.83 12.14,21.23 12.11,21.21
N12386710 on BOTTOM: 25.88,30.99 26.77,31.88 26.77,34.21 27.51,34.95 29.51,34.95 29.84,34.62 29.84,29.59 30.56,28.88 31.93,28.88 31.98,28.83 31.98,26.16 31.72,25.91 29.77,25.91 28.4,27.28 28.4,27.32 27.48,27.32 27.46,27.3 26.11,27.3 25.88,27.53
N12387437 on BOTTOM: 7.57,22.91 5.05,22.91 4.9,22.76 4.9,21.23 4.98,21.16 7.57,21.16

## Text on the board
Ref Des/Silkscreen Bottom: S/N | MAIN BD | Rev.D | DER-836 | 2050 | DTRBD
Ref Des/Silkscreen Top: L | N
User.7: Please Delete these pins. | 1 NONPLATED SLOTS. | 4 PLATED SLOTS. | 11.  TRACE SPACE +/- 0.003" | 13. 2 LAYERS BOARD TOP,AND,BOT.
User.10: FIGURE | FINISHED_SIZE | 12.012 | 20.0 | 24.02 | 25.0 | 30.0 | 32.012 | 40.0 | 67.988 | 57.091x23.618 | 68.902x23.618 | ROTATION | - | 90.000 | DRILL CHART: TOP to BOTTOM | ALL UNITS ARE IN MILS | TOLERANCE_DRILL | +0.0/-0.0 | +2.988/-2.988 | TOLERANCE_TRAVEL | PLATED | QTY | 14 | 26 | 4 | 2 | 1 | 7
